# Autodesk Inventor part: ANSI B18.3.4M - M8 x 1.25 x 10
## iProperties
Shininess: 64.0
Length Units: 11272
Angle Units: 11279
Time Units: 11290
Mass Units: 11286
Length Display Precision: 3
Angle Display Precision: 2
Compacted: True
Part Number: ANSI B18.3.4M - M8 x 1.25 x 10
Document SubType Name: Modeling
Created: 2002-11
Designer: E. MOSS
Density: 0.0
Volumn: 0.0
Area: 0.0
PropertySet Name: Model Information
Control State: 0
Master: False
Checked Out: False
Author: E. MOSS
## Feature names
1. Base1
